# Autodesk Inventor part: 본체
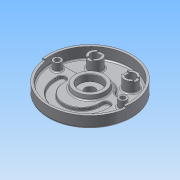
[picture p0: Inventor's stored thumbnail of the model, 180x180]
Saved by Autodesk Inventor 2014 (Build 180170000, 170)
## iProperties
Created: 2015-06
Part Number: 본체
Material: 알루미늄 6061
Document SubType Name: Modeling
Designer: Administrator
Density: 2.71 g/cm^3
Appearance: 알루미늄 - 평지
Mass: 1134.78 g
Surface Area: 1055.53 cm^2
Volume: 418.739 cm^3
Author: Administrator
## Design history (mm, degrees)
sketch "스케치1"
  geometry: C1 r 95 at (0, 0); 1 further point
  constraints: 1 centre point, 1 coincident
  dimensions: "d0" = 190 diameter of C1
extrude "돌출1" new body sketch "스케치1" distance "d1" = 32; taper "d2" = 0 deg
sketch "스케치2"
  geometry: L1 (-88.566, 16)-(-38.833, 16); L2 (38.833, 16)-(88.566, 16); C1 r 95 at (0, 0) reference; A1 r 90 centre (0, 0) between (88.566, 16) and (-88.566, 16); A2 r 42 centre (0, 0) between (38.833, 16) and (-38.833, 16)
  constraints: 4 end point, 4 point on circle, 2 centre point, 2 coincident, 2 collinear, 1 horizontal
  dimensions: "d3" = 180 diameter of A1; "d4" = 84 diameter of A2; "d5" = 16 distance from line of C1.centre L1
extrude "돌출2" cut sketch "스케치2" distance "d6" = 25; taper "d7" = 0 deg
fillet "모깎기1" dims "d8" = 10
sketch "스케치3"
  geometry: C1 r 15 at (-40, 52); C2 r 15 at (40, 52); A1 r 90 centre (0, 0) between (85.114, 29.25) and (-85.114, 29.25) reference
  constraints: 2 centre point, 1 equal radius, 1 horizontal alignment
  dimensions: "d9" = 80 distance of C2.centre C1.centre; "d10" = 40 horizontal distance of A1.centre C1.centre; "d11" = 52 vertical distance of A1.centre C2.centre; "d12" = 30 diameter of C1
extrude "돌출3" join sketch "스케치3" distance "d13" = 25; taper "d14" = 0 deg
node "작업 평면1"
sketch "스케치4"
  geometry: C1 r 15 at (0, 0) reference; C2 r 15 at (80, 0) reference; C3 r 10 at (0, 0); C4 r 10 at (80, 0); 1 further point
  constraints: 2 centre point, 2 coincident
  dimensions: "d16" = 20 diameter of C3; "d17" = 20 diameter of C4
extrude "돌출4" cut sketch "스케치4" stored distance "d18" = 25; taper "d19" = 0 deg
sketch "스케치5"
  geometry: L1 (-6, 13.748)-(-6, -13.748); L2 (6, 13.748)-(6, -13.748); L3 (66.252, 6)-(93.748, 6); L4 (66.252, -6)-(93.748, -6); C1 r 10 at (0, 0) reference; C2 r 10 at (80, 0) reference; A1 r 15 centre (0, 0) between (-6, 13.748) and (-6, -13.748) reference; A2 r 15 centre (80, 0) between (66.252, 6) and (93.748, 6) reference; 1 further point
  constraints: 8 end point, 8 point on circle, 2 parallel, 1 perpendicular, 1 vertical
  dimensions: "d20" = 12 distance between parallel lines of L2 L1; "d21" = 6 distance from line of A1.centre L1; "d22" = 12 distance between parallel lines of L4 L3; "d23" = 6 distance from line of L4 C2.centre
extrude "돌출5" cut sketch "스케치5" distance "d24" = 3; taper "d25" = 0 deg
sketch "스케치6"
  geometry: L1 (-45.033, 16)-(-75.657, 16) reference; L2 (75.657, 16)-(45.033, 16) reference; C1 r 95 at (0, 0) reference; A1 r 10 centre (-75.657, 26) between (-85.114, 29.25) and (-75.657, 16) reference; A2 r 90 centre (0, 0) between (85.114, 29.25) and (-85.114, 29.25) reference; A3 r 10 centre (75.657, 26) between (75.657, 16) and (85.114, 29.25) reference; A4 r 10 centre (45.033, 26) between (36.373, 21) and (45.033, 16) reference; A5 r 42 centre (0, 0) between (36.373, 21) and (-36.373, 21) reference; A6 r 10 centre (-45.033, 26) between (-45.033, 16) and (-36.373, 21) reference; 1 further point
  constraints: 1 coincident, 3 other
extrude "돌출6" cut sketch "스케치6" distance "d26" = 18; taper "d27" = 0 deg
sketch "스케치7"
  geometry: C1 r 35 at (0, 0); A1 r 42 centre (0, 0) between (36.373, 21) and (-36.373, 21) reference
  constraints: 1 centre point, 1 coincident
  dimensions: "d28" = 70 diameter of C1
extrude "돌출7" join sketch "스케치7" distance "d29" = 10; taper "d30" = -10 deg
sketch "스케치8"
  geometry: C1 r 95 at (0, 0) reference; C2 r 26 at (0, 0)
  constraints: 1 centre point, 1 coincident
  dimensions: "d31" = 52 diameter of C2
extrude "돌출8" join sketch "스케치8" distance "d32" = 12; taper "d33" = -15 deg
hole "구멍1" diameter "d36" = 23; stored, may be unused: countersink angle "d40" = 90 deg, drill point angle "d42" = 0 deg; dims "d34" = 10, "d35" = 10, "d37" = 6, "d38" = 50, "d39" = 15, "d41" = 8
sketch "스케치9"
  geometry: C1 r 35 at (0, 0) reference; C2 r 9 at (-74, 0); C3 r 9 at (74, 0)
  constraints: 2 centre point, 2 horizontal alignment, 1 equal radius
  dimensions: "d43" = 148 distance of C3.centre C2.centre; "d44" = 74 distance of C1.centre C2.centre; "d45" = 18 diameter of C2
extrude "돌출9" join sketch "스케치9" distance "d46" = 18; taper "d47" = 0 deg
sketch "스케치10"
  geometry: C1 r 26 at (0, 0) reference; C2 r 10 at (40, 52) reference; C3 r 10 at (-40, 52) reference; C4 r 95 at (0, 0) reference; C5 r 9 at (-74, 0) reference; C6 r 9 at (74, 0) reference; 2 further points
  constraints: 2 coincident
hole "구멍2" sketch "스케치10" at (-74, 0), (74, 0) diameter "d48" = 11; stored, may be unused: countersink angle "d52" = 90 deg, drill point angle "d54" = 0 deg; dims "d49" = 6, "d50" = 18, "d51" = 11, "d53" = 8
sketch "스케치11"
  geometry: L1 (-75.657, 16)-(-45.033, 16) reference; L2 (-59, -19)-(59, -19); L3 (-59, -19)-(-59, -14); L4 (-41, -19)-(-41, -14); L5 (41, -19)-(41, -14); L6 (59, -19)-(59, -14); C1 r 35 at (0, 0) reference; A1 r 41 centre (0, -19) between (-41, -19) and (41, -19); A2 r 59 centre (0, -19) between (-59, -19) and (59, -19); A3 r 9 centre (-50, -14) between (-41, -14) and (-59, -14); A4 r 9 centre (50, -14) between (59, -14) and (41, -14)
  constraints: 10 end point, 8 point on circle, 8 tangent, 7 parallel, 4 centre point, 2 point on line, 1 coincident, 1 perpendicular, 1 vertical alignment
  dimensions: "d57" = 19 distance of C1.centre A1.centre; "d59" = 59 radius of A2; "d60" = 41 radius of A1; "d61" = 5 distance of L2.start L3.end
extrude "돌출10" cut sketch "스케치11" distance "d62" = 7; taper "d63" = 0 deg
sketch "스케치12"
  geometry: C1 r 95 at (0, 0) reference; C2 r 68 at (0, 0)
  constraints: 1 centre point, 1 coincident, 1 other
  dimensions: "d66" = 136 diameter of C2
feature "엠보싱1" sketch "스케치12" dims "d67" = 0.5, "d68" = 0
sketch "스케치13"
  geometry: L1 (-95, 0)-(95, 0); L2 (0, 0)-(-94.075, -13.221); L3 (0, 0)-(94.075, -13.221); C1 r 90 at (0, 0) reference; A1 r 95 centre (0, 0) between (-95, 0) and (95, 0) reference; A2 r 95 centre (0, 0) between (-94.075, -13.221) and (94.075, -13.221); A3 r 90 centre (0, 0) between (-89.124, -12.526) and (89.124, -12.526)
  constraints: 8 point on circle, 6 end point, 2 centre point, 2 coincident, 2 concentric, 2 point on line, 1 horizontal
  dimensions: "d69" = 190 distance of L1.start L1.end; "d72" = 8 deg angle of L3 L1; "d73" = 8 deg angle of L2 L1
extrude "돌출11" cut sketch "스케치13" distance "d74" = 5; taper "d75" = 0 deg
fillet "모깎기2" dims "d76" = 3
chamfer "모따기1" distance "d77" = 1; stored, may be unused: second distance "d78" = 2, angle "d79" = 45 deg
fillet "모깎기3" dims "d80" = 1
chamfer "모따기2" distance "d81" = 1; stored, may be unused: second distance "d82" = 2, angle "d83" = 45 deg
fillet "모깎기4" dims "d84" = 5
fillet "모깎기5" dims "d85" = 3
fillet "모깎기6" dims "d86" = 0.3
fillet "모깎기7" dims "d87" = 3
fillet "모깎기8" dims "d88" = 3
fillet "모깎기9" dims "d89" = 3
fillet "모깎기10" dims "d90" = 3
node "솔리드1"
node "투영된 루프1"
node "투영된 루프2"
node "투영된 루프3"
node "투영된 루프4"
other parameters: "d15" = 0, "d55" = 59, "d56" = 41
